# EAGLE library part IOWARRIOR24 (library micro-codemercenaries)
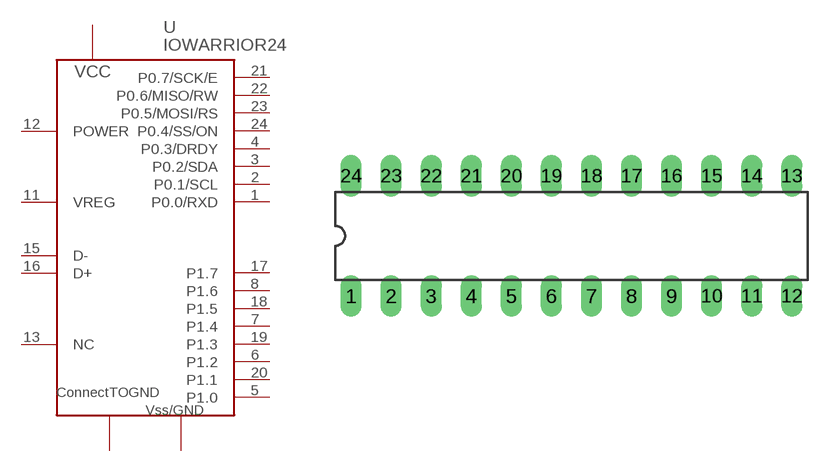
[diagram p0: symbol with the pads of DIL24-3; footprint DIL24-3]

Designator prefix -

## IOWARRIOR24DIL24  [DIL24-3]
1  P0.0/RXD
2  P0.1/SCL
3  P0.2/SDA
4  P0.3/DRDY
5  P1.0
6  P1.2
7  P1.4
8  P1.6
9  VSS  pwr
10  GND
11  VREG
12  POWER
13  NC  nc
14  VCC  pwr
15  D-
16  D+
17  P1.7
18  P1.5
19  P1.3
20  P1.1
21  P0.7/SCK/E
22  P0.6/MISO/RW
23  P0.5/MOSI/RS
24  P0.4/SS/ON

## Footprint DIL24-3 (pad centres in mm)
Dual In Line Package 0.3 inch
drill 0.813 long: 1 -13.97,-3.81; 2 -11.43,-3.81; 3 -8.89,-3.81; 4 -6.35,-3.81; 5 -3.81,-3.81; 6 -1.27,-3.81; 7 1.27,-3.81; 8 3.81,-3.81; 9 6.35,-3.81; 10 8.89,-3.81; 11 11.43,-3.81; 12 13.97,-3.81; 13 13.97,3.81; 14 11.43,3.81; 15 8.89,3.81; 16 6.35,3.81; 17 3.81,3.81; 18 1.27,3.81; 19 -1.27,3.81; 20 -3.81,3.81; 21 -6.35,3.81; 22 -8.89,3.81; 23 -11.43,3.81; 24 -13.97,3.81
